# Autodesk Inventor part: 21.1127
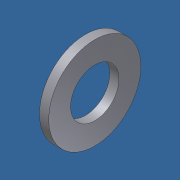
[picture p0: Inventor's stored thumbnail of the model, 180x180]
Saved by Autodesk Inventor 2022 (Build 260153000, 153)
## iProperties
Created: 2006-02
Part Number: 21.1127
Material: Steel, Mild
Description: M8 ROUND WASHER
Document SubType Name: Modeling
Standard: DIN 125
Designer: Andy Moles
Standards Organization: DIN
Language: en-US
Size Designation: A 8.4
Categories: <MemberInstance><Categories><Category DisplayName="Fasteners" InternalName="e4da775c-781d-43d5-af7c-5136215cf5a6" Mnemonic="FSTN"><Category DisplayName="Washers
Mass: 1.82929 g
Surface Area: 4.13936 cm^2
Volume: 0.233031 cm^3
Density: 7.85 g/cm^3
Vendor: S
Appearance: Zinc
Author: Andy Moles
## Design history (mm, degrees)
sketch "Sketch"
  geometry: C1 r 8 at (0, 0); C2 r 4.2 at (0, 0); 1 further point
  constraints: 2 centre point, 2 coincident
  dimensions: "d0" = 8.4 diameter of C2 (= SD1); "d1" = 16 diameter of C1 (= SD2)
extrude "Body" new body sketch "Sketch" distance "d2" = 1.6 (= SD); taper "d3" = 0 deg
workaxis "Work Axis1"
workplane "Work Plane1"
body "Solid1"
other parameters: "SD1" = 8.4 [user parameter; used in 1 equation term], "SD2" = 16 [user parameter; used in 1 equation term], "SD" = 1.6 [user parameter; used in 1 equation term], "d4" = 0, "d5" = 0, "d6" = 0, "d7" = 0, "NND" = 8 [user parameter]
